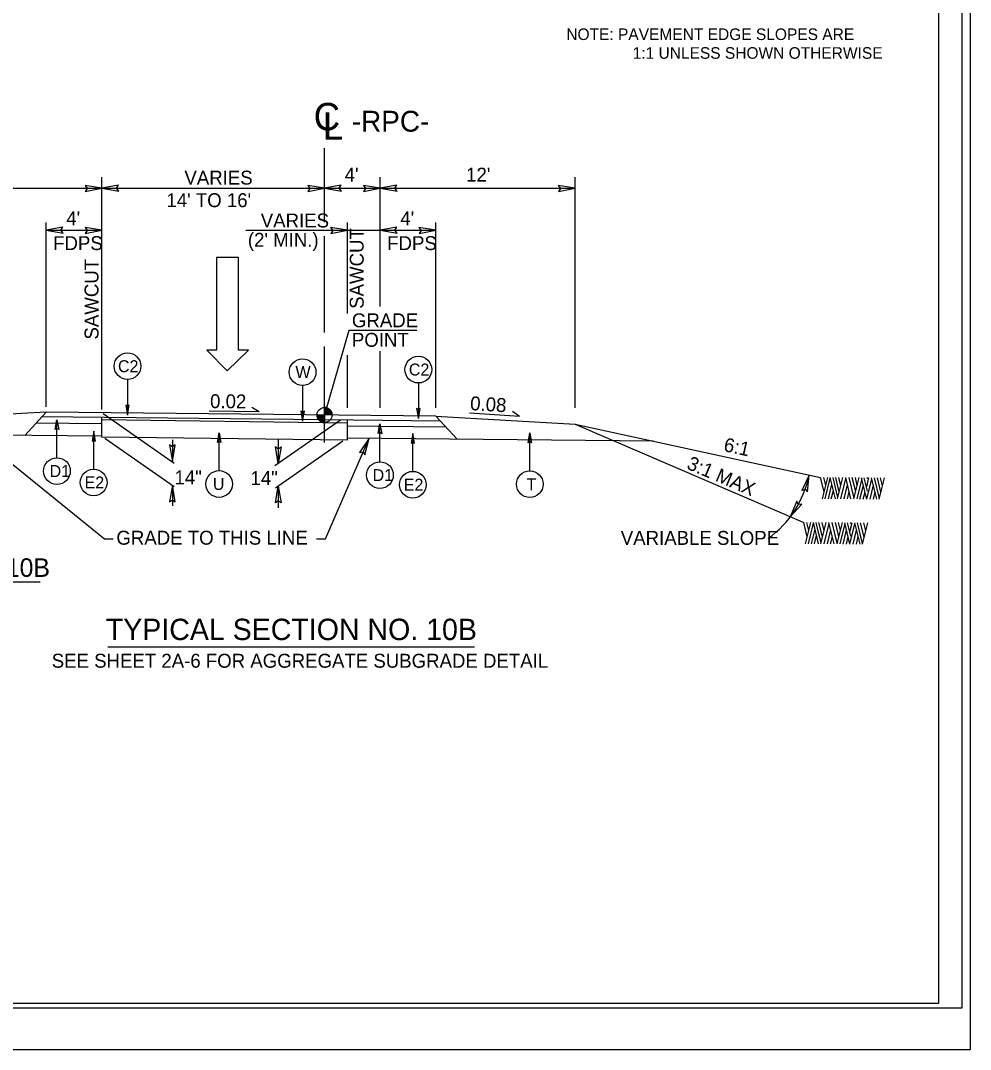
# Model space of a CAD drawing. Extents: x 573748 to 574632, y -54663 to -53209.
# Drawn here: x 574178.6 to 574281, y -54368.7 to -54257.8 of the extents above; entities that cross this region are included whole.
import ezdxf

# ---------------------------------------------------------------- set-up
doc = ezdxf.new("R2010")
doc.units = 0
for name, color, linetype in [('Prop Dimension', 7, 'Continuous'), ('Prop Dimension Text', 7, 'Continuous'), ('Prop Lane Arrow CELL', 7, 'Continuous'), ('Prop Pavement Schedule Description CELL', 7, 'Continuous'), ('Prop Terminator CELL', 7, 'Continuous'), ('Sheet Cutting Line CELL', 7, 'Continuous'), ('Sheet Plot Border Inside CELL', 7, 'Continuous'), ('Sheet Plot Border Outside CELL', 7, 'Continuous'), ('Sheet Typical CELL', 7, 'Continuous'), ('Typical Arrow Superelevation CELL', 7, 'Continuous'), ('Typical Grade Point Symbol CELL', 7, 'Continuous'), ('Typical Hinge Slope Arterial CELL', 7, 'Continuous'), ('Typical ID Circle CELL', 7, 'Continuous'), ('Typical Pavement Slope CELL', 7, 'Continuous'), ('Typical Slope Point Local CELL', 7, 'Continuous'), ('Typical Terminator CELL', 7, 'Continuous'), ('Typical Text Centerline CELL', 7, 'Continuous'), ('Typical Text General CELL', 7, 'Continuous'), ('Typical Text ID Circle CELL', 7, 'Continuous'), ('Typical Text Label CELL', 7, 'Continuous')]:
    doc.layers.add(name, color=color, linetype=linetype)

# ---------------------------------------------------------------- blocks, each defined once
blk = doc.blocks.new('CENTERLINE TEXT CL')
at = {"layer": 'Typical Text Centerline CELL'}
blk.add_text('C', height=1.64, dxfattribs=at).set_placement((-0.546, -0.261))
blk.add_text('L', height=1.641, rotation=359.9469, dxfattribs=at).set_placement((-0.001, -0.821))

msp = doc.modelspace()

# ---------------------------------------------------------------- linework, layer by layer
at = {"layer": 'Prop Dimension'}
for p, q in [((574211.37, -54279.5), (574211.37, -54271.54)), ((574187.37, -54299.7), (574187.37, -54274.65)), ((574217.37, -54288.6), (574217.37, -54274.65)), ((574238.37, -54299.5), (574238.37, -54274.65)), ((574166.37, -54275.85), (574187.37, -54275.85)), ((574187.37, -54275.85), (574211.37, -54275.85)), ((574211.37, -54275.85), (574217.37, -54275.85)), ((574217.37, -54275.85), (574238.37, -54275.85)), ((574181.37, -54299.4), (574181.37, -54279.55)), ((574213.83, -54289.33), (574213.83, -54279.55)), ((574223.37, -54299.5), (574223.37, -54279.55)), ((574181.37, -54280.38), (574187.37, -54280.38)), ((574202.87, -54280.38), (574217.37, -54280.38)), ((574217.37, -54280.38), (574223.35, -54280.38)), ((574211.37, -54291.4), (574211.37, -54281.01)), ((574211.37, -54303.26), (574211.37, -54292.89)), ((574213.83, -54299.5), (574213.83, -54293.85)), ((574217.37, -54299.5), (574217.37, -54293.42)), ((574187.51, -54300.13), (574195.17, -54305.46)), ((574213.83, -54301.16), (574187.37, -54300.82)), ((574187.37, -54302.66), (574187.37, -54300.82)), ((574213.09, -54300.83), (574205.99, -54305.77)), ((574213.83, -54303), (574187.37, -54302.66)), ((574187.69, -54302.79), (574195.17, -54307.99)), ((574213.83, -54303), (574213.83, -54302.76)), ((574194.96, -54302.96), (574194.96, -54305.31)), ((574213.33, -54303.12), (574206.08, -54308.16)), ((574206.38, -54302.9), (574206.38, -54305.5)), ((574194.96, -54307.84), (574194.96, -54310.09)), ((574206.38, -54307.95), (574206.38, -54310.29))]:
    msp.add_line(p, q, dxfattribs=at)
for points in [[(574221.3, -54291.17), (574213.99, -54291.17), (574211.37, -54300.28)], [(574188.59, -54313.68), (574187.63, -54313.68), (574173.75, -54302.42)], [(574210.5, -54313.63), (574211.45, -54313.63), (574216.16, -54302.79)]]:
    msp.add_lwpolyline(points, dxfattribs=at)
msp.add_arc((574252.69, -54304.55), 11.12, 305.7211, 348.569, dxfattribs=at)
at = {"layer": 'Prop Lane Arrow CELL'}
for p, q in [((574199.73, -54283.31), (574199.73, -54293.28)), ((574202.08, -54283.31), (574199.73, -54283.31)), ((574202.08, -54293.28), (574202.08, -54283.31)), ((574199.73, -54293.28), (574198.66, -54293.28)), ((574198.66, -54293.28), (574200.87, -54295.53)), ((574200.87, -54295.53), (574203.15, -54293.28)), ((574203.15, -54293.28), (574202.08, -54293.28))]:
    msp.add_line(p, q, dxfattribs=at)
at = {"layer": 'Prop Terminator CELL'}
for points in [[(574185.57, -54276.18), (574187.37, -54275.85), (574185.55, -54275.55), (574185.79, -54275.87)], [(574189.16, -54275.52), (574187.37, -54275.85), (574189.18, -54276.15), (574188.95, -54275.83)], [(574209.57, -54276.18), (574211.37, -54275.85), (574209.55, -54275.55), (574209.79, -54275.87)], [(574213.16, -54275.52), (574211.37, -54275.85), (574213.18, -54276.15), (574212.95, -54275.83)], [(574215.57, -54276.18), (574217.37, -54275.85), (574215.55, -54275.55), (574215.79, -54275.87)], [(574219.16, -54275.52), (574217.37, -54275.85), (574219.18, -54276.15), (574218.95, -54275.83)], [(574236.57, -54276.18), (574238.37, -54275.85), (574236.55, -54275.55), (574236.79, -54275.87)], [(574183.16, -54280.05), (574181.37, -54280.38), (574183.18, -54280.68), (574182.95, -54280.36)], [(574185.57, -54280.71), (574187.37, -54280.38), (574185.55, -54280.08), (574185.79, -54280.4)], [(574212.04, -54280.71), (574213.83, -54280.38), (574212.02, -54280.08), (574212.25, -54280.4)], [(574219.16, -54280.05), (574217.37, -54280.38), (574219.18, -54280.68), (574218.95, -54280.36)], [(574221.55, -54280.71), (574223.35, -54280.38), (574221.54, -54280.08), (574221.77, -54280.4)], [(574215.72, -54304.57), (574216.16, -54302.79), (574215.14, -54304.33), (574215.53, -54304.24)], [(574194.65, -54303.51), (574194.96, -54305.31), (574195.28, -54303.5), (574194.96, -54303.73)], [(574206.69, -54303.7), (574206.38, -54305.5), (574206.06, -54303.69), (574206.38, -54303.92)], [(574263.4, -54308.58), (574263.58, -54306.76), (574262.79, -54308.42), (574263.16, -54308.28)], [(574195.27, -54309.64), (574194.96, -54307.84), (574194.64, -54309.65), (574194.96, -54309.42)], [(574206.07, -54309.75), (574206.38, -54307.95), (574206.7, -54309.76), (574206.38, -54309.53)], [(574262.27, -54309.57), (574261.56, -54311.25), (574262.81, -54309.9), (574262.41, -54309.92)]]:
    msp.add_lwpolyline(points, close=True, dxfattribs=at)
at = {"layer": 'Sheet Cutting Line CELL'}
msp.add_line((573944.17, -54368.66), (574280.97, -54368.66), dxfattribs=at)
at = {"layer": 'Sheet Plot Border Inside CELL'}
msp.add_lwpolyline([(574280.07, -54153.15), (573946.77, -54153.15), (573946.77, -54364.17), (574280.07, -54364.17)], close=True, dxfattribs=at)
at = {"layer": 'Sheet Plot Border Outside CELL'}
msp.add_lwpolyline([(574280.97, -54148.66), (573944.17, -54148.66), (573944.17, -54368.66), (574280.97, -54368.66)], close=True, dxfattribs=at)
at = {"layer": 'Sheet Typical CELL'}
msp.add_lwpolyline([(574277.57, -54153.66), (573977.57, -54153.66), (573977.57, -54363.66), (574277.57, -54363.66)], close=True, dxfattribs=at)
at = {"layer": 'Typical Arrow Superelevation CELL'}
for p, q in [((574204.32, -54299.93), (574203.53, -54299.46)), ((574204.32, -54299.93), (574198.92, -54299.88)), ((574232.37, -54300.43), (574226.99, -54300.09)), ((574232.37, -54300.43), (574231.61, -54299.92))]:
    msp.add_line(p, q, dxfattribs=at)
at = {"layer": 'Typical Grade Point Symbol CELL'}
for p, q in [((574211.37, -54300.28), (574211.37, -54299.47)), ((574210.56, -54300.28), (574211.37, -54300.28)), ((574211.36, -54301.08), (574211.37, -54300.28)), ((574211.37, -54300.28), (574211.36, -54301.08)), ((574212.17, -54300.28), (574211.37, -54300.28))]:
    msp.add_line(p, q, dxfattribs=at)
for points in [[(574211.37, -54299.47), (574211.37, -54299.47), (574211.37, -54300.28)], [(574211.39, -54299.47), (574211.39, -54300.28)], [(574211.41, -54299.47), (574211.41, -54300.28)], [(574211.42, -54299.47), (574211.42, -54300.28)], [(574211.44, -54299.48), (574211.44, -54300.28)], [(574211.45, -54299.48), (574211.45, -54300.28)], [(574211.47, -54299.48), (574211.47, -54300.28)], [(574211.49, -54299.48), (574211.49, -54300.28)], [(574211.5, -54299.48), (574211.5, -54300.28)], [(574211.52, -54299.49), (574211.52, -54300.28)], [(574211.53, -54299.49), (574211.53, -54300.28)], [(574211.55, -54299.49), (574211.55, -54300.28)], [(574211.57, -54299.5), (574211.57, -54300.28)], [(574211.58, -54299.5), (574211.58, -54300.28)], [(574211.6, -54299.51), (574211.6, -54300.28)], [(574211.61, -54299.51), (574211.61, -54300.28)], [(574211.63, -54299.52), (574211.63, -54300.28)], [(574211.65, -54299.52), (574211.65, -54300.28)], [(574211.66, -54299.53), (574211.66, -54300.28)], [(574211.68, -54299.54), (574211.68, -54300.28)], [(574211.7, -54299.54), (574211.7, -54300.28)], [(574211.71, -54299.55), (574211.71, -54300.28)], [(574211.73, -54299.56), (574211.73, -54300.28)], [(574210.56, -54300.28), (574210.56, -54300.37)], [(574210.58, -54300.28), (574210.58, -54300.46)], [(574210.6, -54300.28), (574210.6, -54300.52)], [(574210.61, -54300.28), (574210.61, -54300.57)], [(574210.63, -54300.28), (574210.63, -54300.6)], [(574210.64, -54300.28), (574210.64, -54300.64)], [(574210.66, -54300.28), (574210.66, -54300.67)], [(574210.68, -54300.28), (574210.68, -54300.7)], [(574210.69, -54300.28), (574210.69, -54300.72)], [(574210.71, -54300.28), (574210.71, -54300.74)], [(574210.72, -54300.28), (574210.72, -54300.77)], [(574210.74, -54300.28), (574210.74, -54300.79)], [(574210.76, -54300.28), (574210.76, -54300.81)], [(574210.77, -54300.28), (574210.77, -54300.82)], [(574210.79, -54300.28), (574210.79, -54300.84)], [(574210.81, -54300.28), (574210.81, -54300.86)], [(574210.82, -54300.28), (574210.82, -54300.87)], [(574210.84, -54300.28), (574210.84, -54300.89)], [(574210.85, -54300.28), (574210.85, -54300.9)], [(574210.87, -54300.28), (574210.87, -54300.91)], [(574210.89, -54300.28), (574210.89, -54300.93)], [(574210.9, -54300.28), (574210.9, -54300.94)], [(574210.92, -54300.28), (574210.92, -54300.95)], [(574210.93, -54300.28), (574210.93, -54300.96)], [(574210.95, -54300.28), (574210.95, -54300.97)], [(574210.97, -54300.28), (574210.97, -54300.98)], [(574210.98, -54300.28), (574210.98, -54300.99)], [(574211, -54300.28), (574211, -54301)], [(574211.01, -54300.28), (574211.01, -54301)], [(574211.03, -54300.28), (574211.03, -54301.01)], [(574211.05, -54300.28), (574211.05, -54301.02)], [(574211.06, -54300.28), (574211.06, -54301.02)], [(574211.08, -54300.28), (574211.08, -54301.03)], [(574211.1, -54300.28), (574211.1, -54301.04)], [(574211.11, -54300.28), (574211.11, -54301.04)], [(574211.13, -54300.28), (574211.13, -54301.05)], [(574211.14, -54300.28), (574211.14, -54301.05)], [(574211.16, -54300.28), (574211.16, -54301.06)], [(574211.18, -54300.28), (574211.18, -54301.06)], [(574211.19, -54300.28), (574211.19, -54301.06)], [(574211.21, -54300.28), (574211.21, -54301.07)], [(574211.22, -54300.28), (574211.22, -54301.07)], [(574211.24, -54300.28), (574211.24, -54301.07)], [(574211.26, -54300.28), (574211.26, -54301.08)], [(574211.27, -54300.28), (574211.27, -54301.08)], [(574211.29, -54300.28), (574211.29, -54301.08)], [(574211.3, -54300.28), (574211.3, -54301.08)], [(574211.32, -54300.28), (574211.32, -54301.08)], [(574211.34, -54300.28), (574211.34, -54301.08)], [(574211.35, -54300.28), (574211.35, -54301.08), (574211.35, -54301.08)], [(574211.74, -54299.57), (574211.74, -54300.28)], [(574211.76, -54299.58), (574211.76, -54300.28)], [(574211.78, -54299.58), (574211.78, -54300.28)], [(574211.79, -54299.59), (574211.79, -54300.28)], [(574211.81, -54299.6), (574211.81, -54300.28)], [(574211.82, -54299.61), (574211.82, -54300.28)], [(574211.84, -54299.63), (574211.84, -54300.28)], [(574211.86, -54299.64), (574211.86, -54300.28)], [(574211.87, -54299.65), (574211.87, -54300.28)], [(574211.89, -54299.66), (574211.89, -54300.28)], [(574211.9, -54299.68), (574211.9, -54300.28)], [(574211.92, -54299.69), (574211.92, -54300.28)], [(574211.94, -54299.71), (574211.94, -54300.28)], [(574211.95, -54299.73), (574211.95, -54300.28)], [(574211.97, -54299.74), (574211.97, -54300.28)], [(574211.99, -54299.76), (574211.99, -54300.28)], [(574212, -54299.78), (574212, -54300.28)], [(574212.02, -54299.8), (574212.02, -54300.28)], [(574212.03, -54299.83), (574212.03, -54300.28)], [(574212.05, -54299.85), (574212.05, -54300.28)], [(574212.07, -54299.88), (574212.07, -54300.28)], [(574212.08, -54299.91), (574212.08, -54300.28)], [(574212.1, -54299.94), (574212.1, -54300.28)], [(574212.11, -54299.98), (574212.11, -54300.28)], [(574212.13, -54300.02), (574212.13, -54300.28)], [(574212.15, -54300.08), (574212.15, -54300.28)], [(574212.16, -54300.16), (574212.16, -54300.28)]]:
    msp.add_lwpolyline(points, dxfattribs=at)
msp.add_circle((574211.36, -54300.28), 0.806, dxfattribs=at)
for start, end in [(359.9905, 89.9905), (179.9905, 269.9905)]:
    msp.add_arc((574211.36, -54300.28), 0.806, start, end, dxfattribs=at)
at = {"layer": 'Typical Hinge Slope Arterial CELL'}
for q in [(574264.82, -54307.03), (574263.01, -54311.88)]:
    msp.add_line((574238.37, -54301.27), q, dxfattribs=at)
at = {"layer": 'Typical ID Circle CELL'}
for p, q in [((574190.13, -54296.47), (574190.13, -54300.29)), ((574209, -54297.11), (574209, -54300.93)), ((574221.47, -54296.83), (574221.47, -54300.66)), ((574182.52, -54304.88), (574182.52, -54300.8)), ((574217.33, -54305.32), (574217.33, -54301.24)), ((574186.48, -54306.12), (574186.48, -54302.03)), ((574200, -54306.27), (574200, -54302.19)), ((574220.88, -54306.35), (574220.88, -54302.27)), ((574233.48, -54306.3), (574233.48, -54302.22))]:
    msp.add_line(p, q, dxfattribs=at)
for centre in [(574190.13, -54295.02), (574221.47, -54295.39), (574209, -54295.67), (574182.52, -54306.33), (574186.48, -54307.56), (574217.33, -54306.76), (574200, -54307.72), (574220.88, -54307.8), (574233.48, -54307.74)]:
    msp.add_circle(centre, 1.44, dxfattribs=at)
at = {"layer": 'Typical Pavement Slope CELL'}
for p, q in [((574181.37, -54299.97), (574166.37, -54300.84)), ((574179.07, -54302.48), (574181.37, -54299.97)), ((574211.37, -54300.81), (574180.89, -54300.49)), ((574223.37, -54300.4), (574181.37, -54299.97)), ((574187.37, -54302.56), (574187.37, -54300.56)), ((574223.37, -54300.4), (574238.37, -54301.27)), ((574225.65, -54302.89), (574223.37, -54300.4)), ((574187.37, -54301.22), (574180.28, -54301.15)), ((574223.85, -54300.94), (574211.37, -54300.81)), ((574213.83, -54302.77), (574213.83, -54300.83)), ((574224.45, -54301.58), (574213.83, -54301.48)), ((574187.37, -54302.56), (574159.75, -54302.28)), ((574246.82, -54303.11), (574213.83, -54302.77))]:
    msp.add_line(p, q, dxfattribs=at)
at = {"layer": 'Typical Slope Point Local CELL'}
for p, q in [((574265.2, -54308.58), (574264.82, -54307.03)), ((574265.02, -54309.31), (574265.59, -54307.01)), ((574265.38, -54307.89), (574265.17, -54307.03)), ((574265.33, -54309.31), (574265.87, -54307.09)), ((574266.43, -54309.31), (574265.86, -54307.03)), ((574266.43, -54308.09), (574266.17, -54307.03)), ((574266.84, -54308.56), (574266.46, -54307.03)), ((574266.66, -54309.31), (574267.22, -54307.03)), ((574267.01, -54307.9), (574266.8, -54307.03)), ((574267.02, -54309.31), (574267.56, -54307.13)), ((574268.1, -54309.31), (574267.54, -54307.03)), ((574268.44, -54309.24), (574267.89, -54307.03)), ((574268.61, -54308.53), (574268.24, -54307.03)), ((574268.42, -54309.31), (574268.98, -54307.03)), ((574268.77, -54307.87), (574268.57, -54307.03)), ((574268.76, -54309.31), (574269.3, -54307.14)), ((574269.8, -54309.35), (574269.23, -54307.06)), ((574269.88, -54308.49), (574269.53, -54307.06)), ((574269.8, -54308.02), (574270.04, -54307.06)), ((574269.81, -54309.35), (574270.35, -54307.17)), ((574269.88, -54307.17), (574269.86, -54307.06)), ((574269.93, -54307.13), (574269.9, -54307.03)), ((574270.89, -54309.35), (574270.32, -54307.06)), ((574271.17, -54309.27), (574270.62, -54307.06)), ((574271.33, -54308.61), (574270.94, -54307.06)), ((574271.15, -54309.35), (574271.71, -54307.05)), ((574271.5, -54307.93), (574271.29, -54307.06)), ((574265.66, -54309.31), (574266.04, -54307.75)), ((574265.98, -54309.31), (574266.2, -54308.41)), ((574266.69, -54309.17), (574266.43, -54308.09)), ((574267.37, -54309.31), (574267.74, -54307.82)), ((574269.07, -54309.35), (574269.43, -54307.86)), ((574269.82, -54307.9), (574269.8, -54307.81)), ((574270.16, -54309.35), (574270.52, -54307.86)), ((574267.72, -54309.31), (574267.91, -54308.52)), ((574269.42, -54309.35), (574269.61, -54308.58)), ((574270.51, -54309.35), (574270.7, -54308.58)), ((574263.39, -54313.43), (574263.01, -54311.88)), ((574263.21, -54314.16), (574263.77, -54311.86)), ((574263.57, -54312.74), (574263.35, -54311.88)), ((574263.51, -54314.16), (574264.06, -54311.94)), ((574263.85, -54314.16), (574264.23, -54312.6)), ((574264.61, -54314.16), (574264.05, -54311.88)), ((574264.61, -54312.94), (574264.35, -54311.88)), ((574265.03, -54313.4), (574264.65, -54311.88)), ((574264.85, -54314.16), (574265.41, -54311.88)), ((574265.2, -54312.75), (574264.98, -54311.88)), ((574265.21, -54314.16), (574265.75, -54311.98)), ((574265.56, -54314.16), (574265.92, -54312.67)), ((574266.29, -54314.16), (574265.72, -54311.88)), ((574266.62, -54314.09), (574266.08, -54311.88)), ((574266.8, -54313.38), (574266.43, -54311.88)), ((574266.61, -54314.16), (574267.17, -54311.88)), ((574266.96, -54312.72), (574266.75, -54311.88)), ((574266.95, -54314.16), (574267.48, -54311.99)), ((574267.25, -54314.19), (574267.62, -54312.71)), ((574267.99, -54314.19), (574267.42, -54311.91)), ((574268.07, -54313.34), (574267.72, -54311.91)), ((574267.98, -54312.87), (574268.22, -54311.91)), ((574268.01, -54312.75), (574267.98, -54312.66)), ((574267.99, -54314.19), (574268.53, -54312.02)), ((574268.07, -54312.02), (574268.05, -54311.91)), ((574268.11, -54311.98), (574268.09, -54311.88)), ((574268.35, -54314.19), (574268.71, -54312.71)), ((574269.08, -54314.19), (574268.51, -54311.91)), ((574269.35, -54314.12), (574268.81, -54311.91)), ((574269.52, -54313.46), (574269.13, -54311.91)), ((574269.34, -54314.19), (574269.9, -54311.9)), ((574269.69, -54312.78), (574269.48, -54311.91)), ((574264.17, -54314.16), (574264.39, -54313.26)), ((574264.88, -54314.02), (574264.61, -54312.94)), ((574265.9, -54314.16), (574266.09, -54313.37)), ((574267.61, -54314.19), (574267.79, -54313.43)), ((574268.7, -54314.19), (574268.88, -54313.43))]:
    msp.add_line(p, q, dxfattribs=at)
at = {"layer": 'Typical Terminator CELL'}
for points in [[(574189.94, -54299.24), (574190.13, -54300.29), (574190.31, -54299.23), (574190.13, -54299.37)], [(574208.82, -54299.88), (574209, -54300.93), (574209.19, -54299.87), (574209, -54300.01)], [(574221.29, -54299.6), (574221.47, -54300.66), (574221.65, -54299.6), (574221.47, -54299.73)], [(574182.34, -54301.85), (574182.52, -54300.8), (574182.71, -54301.86), (574182.52, -54301.73)], [(574217.15, -54302.29), (574217.33, -54301.24), (574217.52, -54302.3), (574217.33, -54302.16)], [(574186.67, -54303.09), (574186.48, -54302.03), (574186.3, -54303.09), (574186.48, -54302.96)], [(574199.82, -54303.24), (574200, -54302.19), (574200.19, -54303.25), (574200, -54303.12)], [(574221.06, -54303.32), (574220.88, -54302.27), (574220.69, -54303.33), (574220.88, -54303.2)], [(574233.3, -54303.27), (574233.48, -54302.22), (574233.67, -54303.28), (574233.48, -54303.14)]]:
    msp.add_lwpolyline(points, close=True, dxfattribs=at)
at = {"layer": 'Typical Text General CELL'}
msp.add_line((574140.7, -54318.28), (574180.7, -54318.28), dxfattribs=at)
at = {"layer": 'Typical Text Label CELL'}
msp.add_line((574188.02, -54325.26), (574227.53, -54325.26), dxfattribs=at)

# ---------------------------------------------------------------- block references
at = {"layer": 'Prop Dimension', "xscale": 1.8000000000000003, "yscale": 1.8000000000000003}
msp.add_blockref('CENTERLINE TEXT CL', (574211.17, -54269.13), dxfattribs=at)

# ---------------------------------------------------------------- texts
at = {"layer": 'Prop Dimension'}
msp.add_text('GRADE TO THIS LINE', height=1.5, dxfattribs=at).set_placement((574188.93, -54314.26))
at = {"layer": 'Prop Dimension Text'}
for s, height, p in [('-RPC-', 2.25, (574214.3, -54269.75)), ('VARIES', 1.5, (574196.26, -54275.45)), ("4'", 1.5, (574213.53, -54275.13)), ("12'", 1.5, (574226.62, -54275.13)), ("14' TO 16'", 1.5, (574194.32, -54277.88)), ("4'", 1.5, (574183.53, -54279.83)), ("4'", 1.5, (574219.53, -54279.83)), ('VARIES', 1.5, (574204.49, -54280.07)), ("(2' MIN.)", 1.5, (574203.1, -54282.15)), ('FDPS', 1.5, (574182.11, -54282.51)), ('FDPS', 1.5, (574218.11, -54282.51)), ('GRADE', 1.5, (574214.31, -54290.83)), ('POINT', 1.5, (574214.31, -54292.93)), ('14"', 1.5, (574195.19, -54307.76)), ('14"', 1.5, (574203.38, -54307.83)), ('TYPICAL SECTION NO. 10B', 2.3, (574187.79, -54324.54))]:
    msp.add_text(s, height=height, dxfattribs=at).set_placement(p)
for s, rotation, p in [('SAWCUT', 90, (574215.58, -54288.84)), ('SAWCUT', 90, (574187, -54292.15)), ('0.02', 359.4781, (574199.02, -54299.54)), ('0.08', 356.4388, (574227.02, -54299.75)), ('6:1', 347.7279, (574254.29, -54304.16)), ('3:1 MAX', 336.8937, (574250.3, -54306.04))]:
    msp.add_text(s, height=1.5, rotation=rotation, dxfattribs=at).set_placement(p)
at = {"layer": 'Prop Pavement Schedule Description CELL'}
for s, p in [('NOTE: PAVEMENT EDGE SLOPES ARE', (574237.42, -54259.87)), ('1:1 UNLESS SHOWN OTHERWISE', (574244.57, -54261.89))]:
    msp.add_text(s, height=1.25, dxfattribs=at).set_placement(p)
at = {"layer": 'Typical Text General CELL'}
for s, height, p in [('VARIABLE SLOPE', 1.5, (574243.29, -54314.28)), ('USE TYPICAL SECTION NO. 10B', 2, (574140.75, -54317.73)), ('SEE SHEET 2A-6 FOR AGGREGATE SUBGRADE DETAIL', 1.5, (574181.96, -54327.52))]:
    msp.add_text(s, height=height, dxfattribs=at).set_placement(p)
at = {"layer": 'Typical Text ID Circle CELL'}
for s, height, p in [('C2', 1.291, (574189.1, -54295.67)), ('W', 1.29, (574208.23, -54296.31)), ('C2', 1.291, (574220.45, -54296.03)), ('D1', 1.291, (574181.73, -54306.97)), ('D1', 1.291, (574216.54, -54307.41)), ('E2', 1.291, (574185.5, -54308.2)), ('U', 1.29, (574199.33, -54308.36)), ('E2', 1.291, (574219.9, -54308.44)), ('T', 1.29, (574233.13, -54308.39))]:
    msp.add_text(s, height=height, dxfattribs=at).set_placement(p)

doc.saveas('drawing.dxf')
